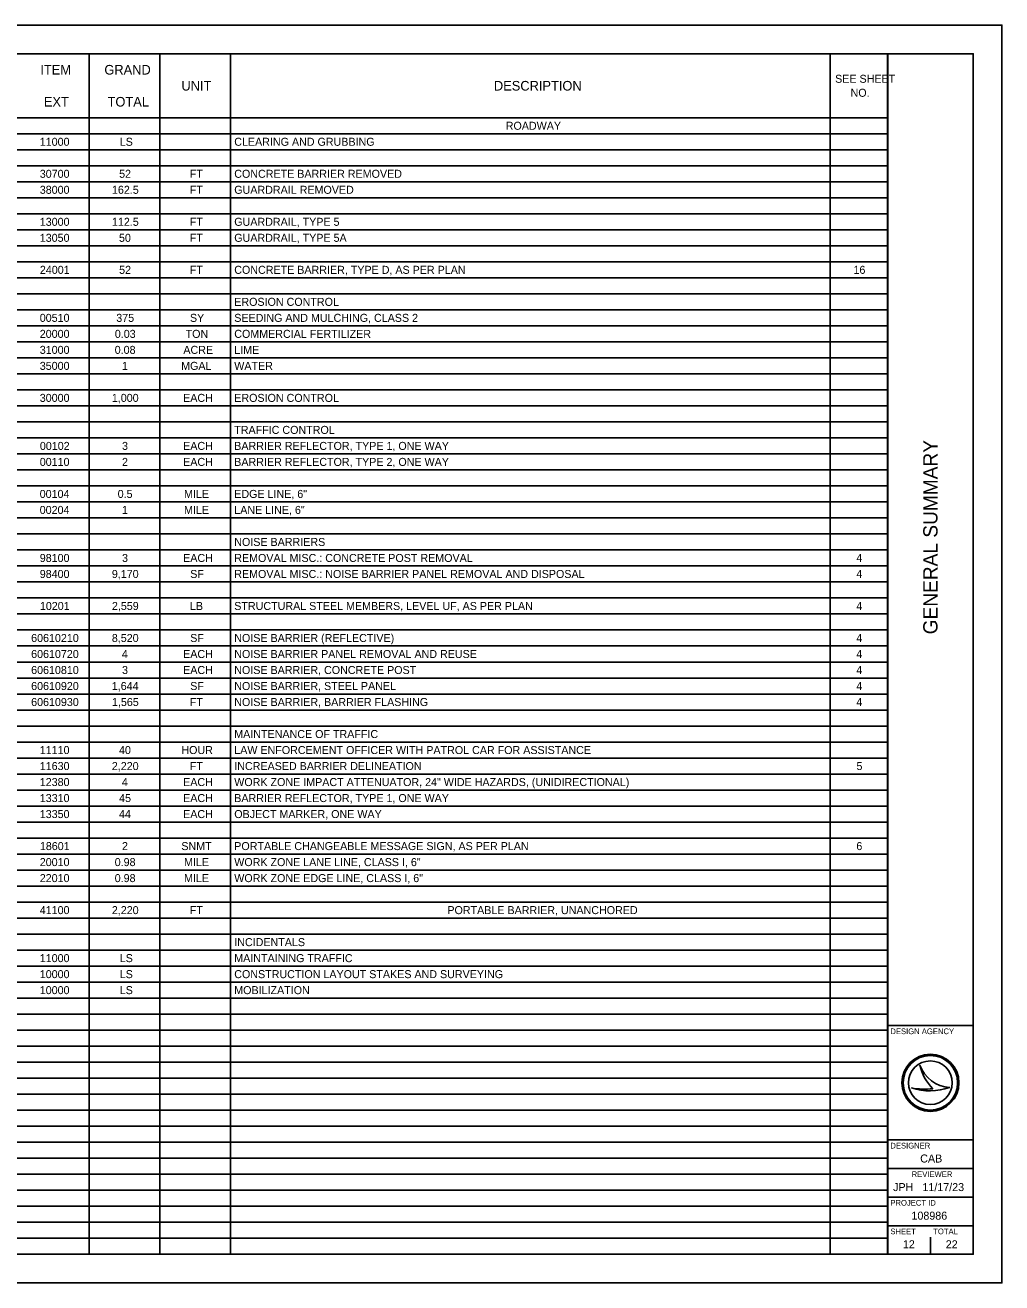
# Model space of a CAD drawing. Extents: x 0 to 34, y 0 to 22.
# Drawn here: x 16.92 to 34, y 0 to 22 of the extents above; entities that cross this region are included whole.
import ezdxf

# ---------------------------------------------------------------- set-up
doc = ezdxf.new("R2010")
doc.units = 0
for name, color, linetype in [('SH_Border', 7, 'Continuous'), ('SH_Cut_Line', 7, 'Continuous'), ('SH_Data', 7, 'Continuous'), ('SH_Text', 7, 'Continuous')]:
    doc.layers.add(name, color=color, linetype=linetype)

msp = doc.modelspace()

# ---------------------------------------------------------------- linework, layer by layer
at = {"layer": 'SH_Border'}
for p, q in [((32, 0.5), (32, 21.5)), ((32, 4.5), (33.5, 4.5)), ((32, 2.5), (33.5, 2.5)), ((32, 2), (33.5, 2)), ((32, 1.5), (33.5, 1.5)), ((32, 1), (33.5, 1))]:
    msp.add_line(p, q, dxfattribs=at)
msp.add_lwpolyline([(1.5, 21.5), (33.5, 21.5), (33.5, 0.5), (1.5, 0.5)], close=True, dxfattribs=at)
at = {"layer": 'SH_Cut_Line'}
msp.add_lwpolyline([(0, 0), (34, 0), (34, 22), (0, 22)], close=True, dxfattribs=at)
at = {"layer": 'SH_Data'}
for p, q in [((1.5, 21.5), (32.004, 21.5)), ((18.036, 21.5), (18.036, 0.5)), ((19.272, 21.5), (19.272, 0.5)), ((20.507, 21.5), (20.507, 0.5)), ((30.999, 21.5), (30.999, 0.5)), ((32.004, 21.5), (32.004, 0.5)), ((1.5, 20.38), (32.004, 20.38)), ((1.5, 20.1), (32.004, 20.1)), ((1.5, 19.82), (32.004, 19.82)), ((1.5, 19.54), (32.004, 19.54)), ((1.5, 19.26), (32.004, 19.26)), ((1.5, 18.98), (32.004, 18.98)), ((1.5, 18.7), (32.004, 18.7)), ((1.5, 18.42), (32.004, 18.42)), ((1.5, 18.14), (32.004, 18.14)), ((1.5, 17.86), (32.004, 17.86)), ((1.5, 17.58), (32.004, 17.58)), ((1.5, 17.3), (32.004, 17.3)), ((1.5, 17.02), (32.004, 17.02)), ((1.5, 16.74), (32.004, 16.74)), ((1.5, 16.46), (32.004, 16.46)), ((1.5, 16.18), (32.004, 16.18)), ((1.5, 15.9), (32.004, 15.9)), ((1.5, 15.62), (32.004, 15.62)), ((1.5, 15.34), (32.004, 15.34)), ((1.5, 15.06), (32.004, 15.06)), ((1.5, 14.78), (32.004, 14.78)), ((1.5, 14.5), (32.004, 14.5)), ((1.5, 14.22), (32.004, 14.22)), ((1.5, 13.94), (32.004, 13.94)), ((1.5, 13.66), (32.004, 13.66)), ((1.5, 13.38), (32.004, 13.38)), ((1.5, 13.1), (32.004, 13.1)), ((1.5, 12.82), (32.004, 12.82)), ((1.5, 12.54), (32.004, 12.54)), ((1.5, 12.26), (32.004, 12.26)), ((1.5, 11.98), (32.004, 11.98)), ((1.5, 11.7), (32.004, 11.7)), ((1.5, 11.42), (32.004, 11.42)), ((1.5, 11.14), (32.004, 11.14)), ((1.5, 10.86), (32.004, 10.86)), ((1.5, 10.58), (32.004, 10.58)), ((1.5, 10.3), (32.004, 10.3)), ((1.5, 10.02), (32.004, 10.02)), ((1.5, 9.74), (32.004, 9.74)), ((1.5, 9.46), (32.004, 9.46)), ((1.5, 9.18), (32.004, 9.18)), ((1.5, 8.9), (32.004, 8.9)), ((1.5, 8.62), (32.004, 8.62)), ((1.5, 8.34), (32.004, 8.34)), ((1.5, 8.06), (32.004, 8.06)), ((1.5, 7.78), (32.004, 7.78)), ((1.5, 7.5), (32.004, 7.5)), ((1.5, 7.22), (32.004, 7.22)), ((1.5, 6.94), (32.004, 6.94)), ((1.5, 6.66), (32.004, 6.66)), ((1.5, 6.38), (32.004, 6.38)), ((1.5, 6.1), (32.004, 6.1)), ((1.5, 5.82), (32.004, 5.82)), ((1.5, 5.54), (32.004, 5.54)), ((1.5, 5.26), (32.004, 5.26)), ((1.5, 4.98), (32.004, 4.98)), ((1.5, 4.7), (32.004, 4.7)), ((1.5, 4.42), (32.004, 4.42)), ((1.5, 4.14), (32.004, 4.14)), ((1.5, 3.86), (32.004, 3.86)), ((32.567, 3.81), (32.567, 3.81)), ((1.5, 3.58), (32.004, 3.58)), ((32.417, 3.41), (32.417, 3.41)), ((32.75, 3.5), (32.75, 3.5)), ((33.087, 3.419), (33.087, 3.419)), ((1.5, 3.3), (32.004, 3.3)), ((1.5, 3.02), (32.004, 3.02)), ((1.5, 2.74), (32.004, 2.74)), ((1.5, 2.46), (32.004, 2.46)), ((1.5, 2.18), (32.004, 2.18)), ((1.5, 1.9), (32.004, 1.9)), ((1.5, 1.62), (32.004, 1.62)), ((1.5, 1.34), (32.004, 1.34)), ((1.5, 1.06), (32.004, 1.06)), ((1.5, 0.78), (32.004, 0.78)), ((32.375, 0.675), (32.375, 0.675)), ((32.75, 0.5), (32.75, 0.8)), ((1.5, 0.5), (32.004, 0.5))]:
    msp.add_line(p, q, dxfattribs=at)
for radius in [0.5, 0.477, 0.477, 0.382]:
    msp.add_circle((32.75, 3.5), radius, dxfattribs=at)
for centre, radius, start, end in [((33.116, 3.998), 0.58, 198.9257, 198.9319), ((33.347, 3.97), 0.796, 191.6379, 191.6421), ((33.116, 3.998), 0.58, 198.9319, 267.1657), ((33.347, 3.97), 0.796, 191.6421, 226.0947), ((32.739, 4.37), 1.013, 251.4576, 290.0832), ((32.648, 4.654), 1.266, 259.4964, 259.4995), ((32.739, 4.37), 1.013, 251.4527, 251.4576), ((32.648, 4.654), 1.266, 259.4995, 276.6672)]:
    msp.add_arc(centre, radius, start, end, dxfattribs=at)

# ---------------------------------------------------------------- texts
msp.add_text('GENERAL SUMMARY', height=0.25, rotation=90, dxfattribs=at).set_placement((32.875, 11.344))
for s, height, p in [('DESIGN AGENCY', 0.1, (32.05, 4.35)), ('DESIGNER', 0.1, (32.05, 2.35)), ('CAB', 0.14, (32.572, 2.105)), ('REVIEWER', 0.1, (32.422, 1.85)), ('JPH', 0.14, (32.098, 1.605)), ('11/17/23', 0.14, (32.611, 1.605)), ('PROJECT ID', 0.1, (32.05, 1.35)), ('108986', 0.14, (32.419, 1.105)), ('SHEET', 0.1, (32.05, 0.85)), ('TOTAL', 0.1, (32.8, 0.85)), ('12', 0.14, (32.269, 0.605)), ('22', 0.14, (33.019, 0.605))]:
    msp.add_text(s, height=height, dxfattribs=at).set_placement(p)
at = {"layer": 'SH_Text'}
for s, height, p in [('ITEM', 0.168, (17.181, 21.136)), ('GRAND', 0.168, (18.301, 21.136)), ('SEE SHEET ', 0.14, (31.084, 20.992)), ('UNIT', 0.168, (19.649, 20.856)), ('DESCRIPTION', 0.168, (25.115, 20.856)), ('EXT', 0.168, (17.242, 20.576)), ('TOTAL', 0.168, (18.357, 20.576)), ('NO.', 0.14, (31.354, 20.747)), ('ROADWAY', 0.14, (25.322, 20.17)), ('11000', 0.14, (17.171, 19.89)), ('LS', 0.14, (18.57, 19.89)), ('CLEARING AND GRUBBING', 0.14, (20.573, 19.89)), ('30700', 0.14, (17.171, 19.33)), ('52', 0.14, (18.559, 19.33)), ('FT', 0.14, (19.796, 19.33)), ('CONCRETE BARRIER REMOVED', 0.14, (20.573, 19.33)), ('38000', 0.14, (17.171, 19.05)), ('162.5', 0.14, (18.434, 19.05)), ('FT', 0.14, (19.796, 19.05)), ('GUARDRAIL REMOVED', 0.14, (20.573, 19.05)), ('13000', 0.14, (17.171, 18.49)), ('112.5', 0.14, (18.434, 18.49)), ('FT', 0.14, (19.796, 18.49)), ('GUARDRAIL, TYPE 5', 0.14, (20.573, 18.49)), ('13050', 0.14, (17.171, 18.21)), ('50', 0.14, (18.557, 18.21)), ('FT', 0.14, (19.796, 18.21)), ('GUARDRAIL, TYPE 5A', 0.14, (20.573, 18.21)), ('24001', 0.14, (17.173, 17.65)), ('52', 0.14, (18.559, 17.65)), ('FT', 0.14, (19.796, 17.65)), ('CONCRETE BARRIER, TYPE D, AS PER PLAN', 0.14, (20.573, 17.65)), ('16', 0.14, (31.405, 17.65)), ('EROSION CONTROL', 0.14, (20.573, 17.09)), ('00510', 0.14, (17.171, 16.81)), ('375', 0.14, (18.509, 16.81)), ('SY', 0.14, (19.798, 16.81)), ('SEEDING AND MULCHING, CLASS 2', 0.14, (20.573, 16.81)), ('20000', 0.14, (17.171, 16.53)), ('0.03', 0.14, (18.484, 16.53)), ('TON', 0.14, (19.722, 16.53)), ('COMMERCIAL FERTILIZER', 0.14, (20.573, 16.53)), ('31000', 0.14, (17.171, 16.25)), ('0.08', 0.14, (18.482, 16.25)), ('ACRE', 0.14, (19.683, 16.25)), ('LIME', 0.14, (20.573, 16.25)), ('35000', 0.14, (17.171, 15.97)), ('1', 0.14, (18.609, 15.97)), ('MGAL', 0.14, (19.644, 15.97)), ('WATER', 0.14, (20.573, 15.97)), ('30000', 0.14, (17.171, 15.41)), ('1,000', 0.14, (18.432, 15.41)), ('EACH', 0.14, (19.679, 15.41)), ('EROSION CONTROL', 0.14, (20.573, 15.41)), ('TRAFFIC CONTROL', 0.14, (20.573, 14.85)), ('00102', 0.14, (17.173, 14.57)), ('3', 0.14, (18.61, 14.57)), ('EACH', 0.14, (19.679, 14.57)), ('BARRIER REFLECTOR, TYPE 1, ONE WAY', 0.14, (20.573, 14.57)), ('00110', 0.14, (17.171, 14.29)), ('2', 0.14, (18.609, 14.29)), ('EACH', 0.14, (19.679, 14.29)), ('BARRIER REFLECTOR, TYPE 2, ONE WAY', 0.14, (20.573, 14.29)), ('00104', 0.14, (17.17, 13.73)), ('0.5', 0.14, (18.534, 13.73)), ('MILE', 0.14, (19.695, 13.73)), ('EDGE LINE, 6"', 0.14, (20.573, 13.73)), ('00204', 0.14, (17.17, 13.45)), ('1', 0.14, (18.609, 13.45)), ('MILE', 0.14, (19.695, 13.45)), ('LANE LINE, 6"', 0.14, (20.573, 13.45)), ('NOISE BARRIERS', 0.14, (20.573, 12.89)), ('98100', 0.14, (17.171, 12.61)), ('3', 0.14, (18.61, 12.61)), ('EACH', 0.14, (19.679, 12.61)), ('REMOVAL MISC.: CONCRETE POST REMOVAL', 0.14, (20.573, 12.61)), ('4', 0.14, (31.454, 12.61)), ('98400', 0.14, (17.171, 12.33)), ('9,170', 0.14, (18.432, 12.33)), ('SF', 0.14, (19.803, 12.33)), ('REMOVAL MISC.: NOISE BARRIER PANEL REMOVAL AND DISPOSAL', 0.14, (20.573, 12.33)), ('4', 0.14, (31.454, 12.33)), ('10201', 0.14, (17.173, 11.77)), ('2,559', 0.14, (18.433, 11.77)), ('LB', 0.14, (19.798, 11.77)), ('STRUCTURAL STEEL MEMBERS, LEVEL UF, AS PER PLAN', 0.14, (20.573, 11.77)), ('4', 0.14, (31.454, 11.77)), ('60610210', 0.14, (17.02, 11.21)), ('8,520', 0.14, (18.432, 11.21)), ('SF', 0.14, (19.803, 11.21)), ('NOISE BARRIER (REFLECTIVE)', 0.14, (20.573, 11.21)), ('4', 0.14, (31.454, 11.21)), ('60610720', 0.14, (17.02, 10.93)), ('4', 0.14, (18.607, 10.93)), ('EACH', 0.14, (19.679, 10.93)), ('NOISE BARRIER PANEL REMOVAL AND REUSE', 0.14, (20.573, 10.93)), ('4', 0.14, (31.454, 10.93)), ('60610810', 0.14, (17.02, 10.65)), ('3', 0.14, (18.61, 10.65)), ('EACH', 0.14, (19.679, 10.65)), ('NOISE BARRIER, CONCRETE POST', 0.14, (20.573, 10.65)), ('4', 0.14, (31.454, 10.65)), ('60610920', 0.14, (17.02, 10.37)), ('1,644', 0.14, (18.431, 10.37)), ('SF', 0.14, (19.803, 10.37)), ('NOISE BARRIER, STEEL PANEL', 0.14, (20.573, 10.37)), ('4', 0.14, (31.454, 10.37)), ('60610930', 0.14, (17.02, 10.09)), ('1,565', 0.14, (18.434, 10.09)), ('FT', 0.14, (19.796, 10.09)), ('NOISE BARRIER, BARRIER FLASHING', 0.14, (20.573, 10.09)), ('4', 0.14, (31.454, 10.09)), ('MAINTENANCE OF TRAFFIC', 0.14, (20.573, 9.53)), ('11110', 0.14, (17.171, 9.25)), ('40', 0.14, (18.557, 9.25)), ('HOUR', 0.14, (19.648, 9.25)), ('LAW ENFORCEMENT OFFICER WITH PATROL CAR FOR ASSISTANCE', 0.14, (20.573, 9.25)), ('11630', 0.14, (17.171, 8.97)), ('2,220', 0.14, (18.432, 8.97)), ('FT', 0.14, (19.796, 8.97)), ('INCREASED BARRIER DELINEATION', 0.14, (20.573, 8.97)), ('5', 0.14, (31.457, 8.97)), ('12380', 0.14, (17.171, 8.69)), ('4', 0.14, (18.607, 8.69)), ('EACH', 0.14, (19.679, 8.69)), ('WORK ZONE IMPACT ATTENUATOR, 24" WIDE HAZARDS, (UNIDIRECTIONAL)', 0.14, (20.573, 8.69)), ('13310', 0.14, (17.171, 8.41)), ('45', 0.14, (18.559, 8.41)), ('EACH', 0.14, (19.679, 8.41)), ('BARRIER REFLECTOR, TYPE 1, ONE WAY', 0.14, (20.573, 8.41)), ('13350', 0.14, (17.171, 8.13)), ('44', 0.14, (18.556, 8.13)), ('EACH', 0.14, (19.679, 8.13)), ('OBJECT MARKER, ONE WAY', 0.14, (20.573, 8.13)), ('18601', 0.14, (17.173, 7.57)), ('2', 0.14, (18.609, 7.57)), ('SNMT', 0.14, (19.647, 7.57)), ('PORTABLE CHANGEABLE MESSAGE SIGN, AS PER PLAN', 0.14, (20.573, 7.57)), ('6', 0.14, (31.455, 7.57)), ('20010', 0.14, (17.171, 7.29)), ('0.98', 0.14, (18.482, 7.29)), ('MILE', 0.14, (19.695, 7.29)), ('WORK ZONE LANE LINE, CLASS I, 6"', 0.14, (20.573, 7.29)), ('22010', 0.14, (17.171, 7.01)), ('0.98', 0.14, (18.482, 7.01)), ('MILE', 0.14, (19.695, 7.01)), ('WORK ZONE EDGE LINE, CLASS I, 6"', 0.14, (20.573, 7.01)), ('41100', 0.14, (17.171, 6.45)), ('2,220', 0.14, (18.432, 6.45)), ('FT', 0.14, (19.796, 6.45)), ('PORTABLE BARRIER, UNANCHORED', 0.14, (24.301, 6.45)), ('INCIDENTALS', 0.14, (20.573, 5.89)), ('11000', 0.14, (17.171, 5.61)), ('LS', 0.14, (18.57, 5.61)), ('MAINTAINING TRAFFIC', 0.14, (20.573, 5.61)), ('10000', 0.14, (17.171, 5.33)), ('LS', 0.14, (18.57, 5.33)), ('CONSTRUCTION LAYOUT STAKES AND SURVEYING', 0.14, (20.573, 5.33)), ('10000', 0.14, (17.171, 5.05)), ('LS', 0.14, (18.57, 5.05)), ('MOBILIZATION', 0.14, (20.573, 5.05))]:
    msp.add_text(s, height=height, dxfattribs=at).set_placement(p)

doc.saveas('drawing.dxf')
